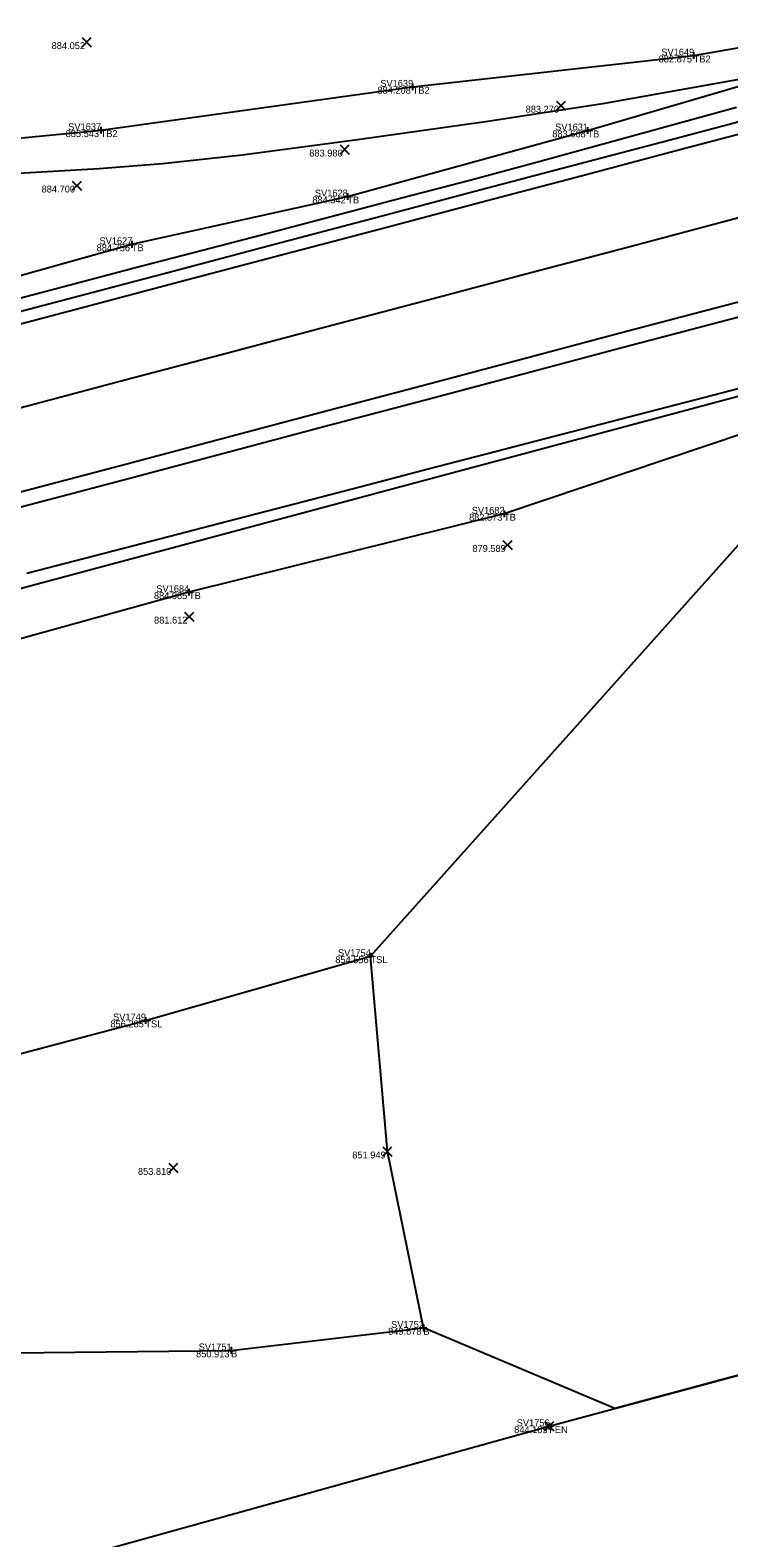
# Model space of a CAD drawing. Extents: x 2125299 to 2129212, y 713100 to 714300.
# Drawn here: x 2127805.3 to 2127906.4, y 713670.1 to 713888.4 of the extents above; entities that cross this region are included whole.
import ezdxf

# ---------------------------------------------------------------- set-up
doc = ezdxf.new("R2010")
doc.units = 0
for name, color, linetype in [('_CIVIL_CONSTRUCTION', 7, 'Continuous'), ('Default', 7, 'Continuous'), ('PV_X_EOP', 7, 'Continuous'), ('PV_X_Shoulder_Rumble_Strip', 7, 'Continuous'), ('RD_X_Fence', 7, 'Continuous'), ('RS_Raster1', 7, 'Continuous'), ('RW_P_Esmt_TMP', 7, 'Continuous'), ('RW_X_Esmt_CH', 7, 'Continuous'), ('RW_X_Fee_WL', 7, 'Continuous'), ('SC_Scratch1', 7, 'Continuous'), ('SC_Scratch2', 7, 'Continuous'), ('SV_X_Break_Lines', 7, 'Continuous'), ('SV_X_Mon_Cells_Found', 7, 'Continuous'), ('SV_X_Text_Elevation', 7, 'Continuous'), ('SV_X_Toe_of_Slope', 7, 'Continuous'), ('SV_X_Top_of_Bank', 7, 'Continuous')]:
    doc.layers.add(name, color=color, linetype=linetype)

msp = doc.modelspace()

# ---------------------------------------------------------------- linework, layer by layer
at = {"layer": '_CIVIL_CONSTRUCTION'}
msp.add_lwpolyline([(2127659.73, 713795.61), (2127674.23, 713799.44), (2127688.74, 713803.28), (2127703.24, 713807.12), (2127717.74, 713810.96), (2127732.24, 713814.8), (2127746.74, 713818.64), (2127761.24, 713822.47), (2127775.74, 713826.31), (2127790.24, 713830.15), (2127804.74, 713833.98), (2127819.24, 713837.82), (2127833.74, 713841.66), (2127848.24, 713845.49), (2127862.75, 713849.33), (2127877.25, 713853.16), (2127891.75, 713857), (2127906.25, 713860.83), (2127920.75, 713864.67)], dxfattribs=at)
at = {"layer": 'Default'}
msp.add_lwpolyline([(2127925.78, 713698.52), (2127889.92, 713688.84), (2127862.23, 713700.52), (2127857.03, 713726.05), (2127854.59, 713754.33), (2127921.84, 713829.55)], dxfattribs=at)
at = {"layer": 'PV_X_EOP'}
for points in [[(2127801.24, 713848.95), (2127810.91, 713851.5), (2127820.58, 713854.03), (2127830.26, 713856.56), (2127839.93, 713859.09), (2127849.61, 713861.62), (2127859.28, 713864.16), (2127868.96, 713866.69), (2127878.61, 713869.3), (2127888.25, 713871.94), (2127897.9, 713874.59), (2127907.54, 713877.24)], [(2127804.86, 713809.77), (2127814.54, 713812.29), (2127824.22, 713814.81), (2127833.89, 713817.32), (2127843.57, 713819.84), (2127853.25, 713822.36), (2127862.93, 713824.88), (2127872.6, 713827.4), (2127882.28, 713829.91), (2127891.96, 713832.43), (2127901.64, 713834.95), (2127911.32, 713837.47)]]:
    msp.add_lwpolyline(points, dxfattribs=at)
at = {"layer": 'PV_X_Shoulder_Rumble_Strip'}
for points in [[(2127652.21, 713807.54), (2127666.7, 713811.39), (2127681.2, 713815.24), (2127695.69, 713819.08), (2127710.19, 713822.92), (2127724.69, 713826.75), (2127739.19, 713830.59), (2127753.68, 713834.42), (2127768.18, 713838.25), (2127782.68, 713842.09), (2127797.18, 713845.92), (2127811.68, 713849.75), (2127826.18, 713853.59), (2127840.68, 713857.42), (2127855.17, 713861.25), (2127869.67, 713865.09), (2127884.17, 713868.92), (2127898.67, 713872.75), (2127913.17, 713876.59), (2127927.67, 713880.42), (2127936.81, 713882.83)], [(2127659.41, 713781.04), (2127673.9, 713784.89), (2127688.4, 713788.73), (2127702.89, 713792.57), (2127717.39, 713796.42), (2127731.89, 713800.26), (2127746.38, 713804.1), (2127760.88, 713807.95), (2127775.37, 713811.79), (2127789.87, 713815.63), (2127804.37, 713819.48), (2127818.86, 713823.32), (2127833.36, 713827.16), (2127847.85, 713831.01), (2127862.35, 713834.85), (2127876.84, 713838.69), (2127891.34, 713842.54), (2127905.84, 713846.37), (2127920.34, 713850.2), (2127928.07, 713852.23)]]:
    msp.add_lwpolyline(points, dxfattribs=at)
at = {"layer": 'RD_X_Fence'}
msp.add_lwpolyline([(2127758.11, 713652.62), (2127783.85, 713659.47), (2127880.44, 713686.28), (2127925.78, 713698.52)], dxfattribs=at)
at = {"layer": 'RS_Raster1'}
msp.add_lwpolyline([(2127665.8, 713847.33), (2127722.38, 713859.86), (2127735.74, 713862.67), (2127747.07, 713864.19), (2127753.51, 713864.63), (2127770.12, 713865.48), (2127798.56, 713867.4), (2127815.33, 713868.4), (2127824.46, 713869.11), (2127836.01, 713870.37), (2127852.68, 713872.56), (2127871.22, 713875.21), (2127888.51, 713877.86), (2127910.9, 713881.86), (2127918.62, 713883.3), (2127925.53, 713884.74), (2127939.36, 713888.03)], dxfattribs=at)
at = {"layer": 'SC_Scratch1'}
msp.add_lwpolyline([(2127133.38, 713627.43), (2127166.26, 713637.18), (2127280.77, 713668.85), (2127395.3, 713699.47), (2127509.42, 713729.99), (2127750.89, 713793.4), (2127929.41, 713841.22)], dxfattribs=at)
at = {"layer": 'SC_Scratch2'}
for points in [[(2127653.02, 713805.95), (2127667.52, 713809.8), (2127682.02, 713813.65), (2127696.52, 713817.5), (2127711.02, 713821.33), (2127725.52, 713825.17), (2127740.02, 713829), (2127754.52, 713832.83), (2127769.02, 713836.67), (2127783.52, 713840.5), (2127798.03, 713844.34), (2127812.53, 713848.17), (2127827.03, 713852.01), (2127841.53, 713855.84), (2127856.03, 713859.67), (2127870.54, 713863.51), (2127885.04, 713867.34), (2127899.54, 713871.18), (2127914.04, 713875.01), (2127928.54, 713878.84), (2127943.04, 713882.68), (2127957.55, 713886.51), (2127972.05, 713890.34)], [(2127658.93, 713783.11), (2127673.43, 713786.96), (2127687.93, 713790.8), (2127702.43, 713794.64), (2127716.93, 713798.49), (2127731.43, 713802.33), (2127745.92, 713806.18), (2127760.42, 713810.02), (2127774.92, 713813.87), (2127789.42, 713817.71), (2127803.92, 713821.55), (2127818.42, 713825.4), (2127832.92, 713829.24), (2127847.42, 713833.09), (2127861.92, 713836.93), (2127876.42, 713840.78), (2127890.92, 713844.62), (2127905.42, 713848.46), (2127919.92, 713852.28)]]:
    msp.add_lwpolyline(points, dxfattribs=at)
at = {"layer": 'SV_X_Break_Lines'}
msp.add_lwpolyline([(2127616.18, 713671.15), (2127652.31, 713680.4), (2127690.28, 713680.39), (2127706.61, 713685.74), (2127738.88, 713689.15), (2127770.05, 713693.72), (2127802.8, 713696.9), (2127834.4, 713697.26), (2127862.23, 713700.52)], dxfattribs=at)
at = {"layer": 'SV_X_Mon_Cells_Found'}
for p, q in [((2127900.84, 713884.74), (2127901.84, 713884.74)), ((2127901.34, 713885.24), (2127901.34, 713884.24)), ((2127901.34, 713884.74), (2127901.34, 713884.74)), ((2127860.18, 713880.21), (2127861.18, 713880.21)), ((2127860.68, 713880.71), (2127860.68, 713879.71)), ((2127860.68, 713880.21), (2127860.68, 713880.21)), ((2127815.04, 713873.93), (2127816.04, 713873.93)), ((2127815.54, 713874.43), (2127815.54, 713873.43)), ((2127815.54, 713873.93), (2127815.54, 713873.93)), ((2127885.48, 713873.89), (2127886.48, 713873.89)), ((2127885.98, 713874.39), (2127885.98, 713873.39)), ((2127885.98, 713873.89), (2127885.98, 713873.89)), ((2127850.73, 713864.33), (2127851.73, 713864.33)), ((2127851.23, 713864.83), (2127851.23, 713863.83)), ((2127851.23, 713864.33), (2127851.23, 713864.33)), ((2127820.05, 713857.91), (2127820.05, 713856.91)), ((2127819.55, 713857.41), (2127820.55, 713857.41)), ((2127820.05, 713857.41), (2127820.05, 713857.41)), ((2127873.4, 713818.39), (2127874.4, 713818.39)), ((2127873.9, 713818.89), (2127873.9, 713817.89)), ((2127873.9, 713818.39), (2127873.9, 713818.39)), ((2127828.31, 713807.54), (2127828.31, 713806.54)), ((2127827.81, 713807.04), (2127828.81, 713807.04)), ((2127828.31, 713807.04), (2127828.31, 713807.04)), ((2127854.09, 713754.33), (2127855.09, 713754.33)), ((2127854.59, 713754.83), (2127854.59, 713753.83)), ((2127854.59, 713754.33), (2127854.59, 713754.33)), ((2127821.51, 713745.03), (2127822.51, 713745.03)), ((2127822.01, 713745.53), (2127822.01, 713744.53)), ((2127822.01, 713745.03), (2127822.01, 713745.03)), ((2127861.73, 713700.52), (2127862.73, 713700.52)), ((2127862.23, 713701.02), (2127862.23, 713700.02)), ((2127862.23, 713700.52), (2127862.23, 713700.52)), ((2127833.9, 713697.26), (2127834.9, 713697.26)), ((2127834.4, 713697.76), (2127834.4, 713696.76)), ((2127834.4, 713697.26), (2127834.4, 713697.26)), ((2127879.94, 713686.28), (2127880.94, 713686.28)), ((2127880.44, 713686.78), (2127880.44, 713685.78)), ((2127880.44, 713686.28), (2127880.44, 713686.28))]:
    msp.add_line(p, q, dxfattribs=at)
at = {"layer": 'SV_X_Text_Elevation'}
for p, q in [((2127812.85, 713886), (2127814.18, 713887.33)), ((2127812.85, 713887.33), (2127814.18, 713886)), ((2127881.47, 713876.81), (2127882.81, 713878.14)), ((2127881.47, 713878.14), (2127882.81, 713876.81)), ((2127850.17, 713870.45), (2127851.5, 713871.79)), ((2127850.17, 713871.79), (2127851.5, 713870.45)), ((2127811.43, 713865.24), (2127812.77, 713866.57)), ((2127811.43, 713866.57), (2127812.77, 713865.24)), ((2127873.74, 713813.2), (2127875.07, 713814.53)), ((2127873.74, 713814.53), (2127875.07, 713813.2)), ((2127827.67, 713802.83), (2127829, 713804.16)), ((2127827.67, 713804.16), (2127829, 713802.83)), ((2127856.36, 713725.38), (2127857.69, 713726.72)), ((2127856.36, 713726.72), (2127857.69, 713725.38)), ((2127825.38, 713723.02), (2127826.71, 713724.35)), ((2127825.38, 713724.35), (2127826.71, 713723.02)), ((2127879.78, 713685.61), (2127881.11, 713686.95)), ((2127879.78, 713686.95), (2127881.11, 713685.61))]:
    msp.add_line(p, q, dxfattribs=at)
at = {"layer": 'SV_X_Toe_of_Slope'}
msp.add_lwpolyline([(2127560.57, 713676.96), (2127620.08, 713691.3), (2127651.95, 713701.51), (2127685.52, 713714.38), (2127712.77, 713721.61), (2127733.87, 713722.46), (2127761.63, 713729.12), (2127790.85, 713736.75), (2127822.01, 713745.03), (2127854.59, 713754.33)], dxfattribs=at)
at = {"layer": 'SV_X_Top_of_Bank'}
for points in [[(2127691.05, 713857.86), (2127708.64, 713865.58), (2127737.13, 713873.46), (2127762.81, 713869.75), (2127785.71, 713871.04), (2127815.54, 713873.93), (2127860.68, 713880.21), (2127901.34, 713884.74), (2127930.61, 713889.81), (2127938.55, 713892.74), (2127941.1, 713904.01), (2127946.04, 713922.91), (2127948.74, 713934.84), (2127960.18, 713949.89), (2127971.8, 713964.93)], [(2127118.3, 713671.13), (2127177.41, 713689.33), (2127235.14, 713704.98), (2127293.81, 713721.23), (2127351.9, 713736.5), (2127410.59, 713750.81), (2127468.4, 713765.95), (2127530.81, 713781.83), (2127585.7, 713797.67), (2127644.65, 713813.57), (2127714.44, 713829.64), (2127739.44, 713835.61), (2127786.69, 713848.08), (2127820.05, 713857.41), (2127851.23, 713864.33), (2127885.98, 713873.89), (2127912.04, 713881.53)], [(2127920.85, 713834.18), (2127873.9, 713818.39), (2127828.31, 713807.04), (2127782.81, 713794.43), (2127731.94, 713780.7), (2127685.41, 713769.5), (2127638.8, 713755.97), (2127588.05, 713743.29)]]:
    msp.add_lwpolyline(points, dxfattribs=at)

# ---------------------------------------------------------------- texts
at = {"layer": 'RW_P_Esmt_TMP'}
for s, p in [('TB2', (2127901.34, 713883.74)), ('TB2', (2127860.68, 713879.21)), ('TB2', (2127815.54, 713872.93)), ('TB', (2127885.98, 713872.89)), ('TB', (2127851.23, 713863.33)), ('TB', (2127820.05, 713856.41)), ('TB', (2127873.9, 713817.39)), ('TB', (2127828.31, 713806.04)), ('TSL', (2127854.59, 713753.33)), ('TSL', (2127822.01, 713744.03)), ('B', (2127862.23, 713699.52)), ('B', (2127834.4, 713696.26)), ('FEN', (2127880.44, 713685.28))]:
    msp.add_text(s, height=1, dxfattribs=at).set_placement(p)
at = {"layer": 'RW_X_Esmt_CH'}
for s, p in [('SV1649', (2127896.66, 713884.74)), ('SV1639', (2127856, 713880.21)), ('SV1637', (2127810.84, 713873.93)), ('SV1631', (2127881.3, 713873.89)), ('SV1628', (2127846.53, 713864.33)), ('SV1627', (2127815.36, 713857.41)), ('SV1682', (2127869.23, 713818.39)), ('SV1684', (2127823.59, 713807.04)), ('SV1754', (2127849.87, 713754.33)), ('SV1749', (2127817.33, 713745.03)), ('SV1752', (2127857.56, 713700.52)), ('SV1751', (2127829.72, 713697.26)), ('SV1756', (2127875.74, 713686.28))]:
    msp.add_text(s, height=1, dxfattribs=at).set_placement(p)
at = {"layer": 'RW_X_Fee_WL'}
for s, p in [('884.052', (2127808.44, 713885.67)), ('882.875', (2127896.27, 713883.74)), ('884.208', (2127855.58, 713879.21)), ('883.270', (2127877.03, 713876.47)), ('885.543', (2127810.47, 713872.93)), ('883.668', (2127880.88, 713872.89)), ('883.980', (2127845.72, 713870.12)), ('884.700', (2127806.99, 713864.91)), ('884.342', (2127846.16, 713863.33)), ('884.756', (2127814.95, 713856.41)), ('882.573', (2127868.84, 713817.39)), ('879.589', (2127869.32, 713812.87)), ('884.085', (2127823.24, 713806.04)), ('881.612', (2127823.26, 713802.5)), ('854.556', (2127849.48, 713753.33)), ('856.285', (2127816.94, 713744.03)), ('851.949', (2127851.94, 713725.05)), ('853.810', (2127820.93, 713722.68)), ('849.678', (2127857.13, 713699.52)), ('850.913', (2127829.34, 713696.26)), ('844.105', (2127875.37, 713685.28)), ('844.105', (2127875.37, 713685.28))]:
    msp.add_text(s, height=1, dxfattribs=at).set_placement(p)

doc.saveas('drawing.dxf')
